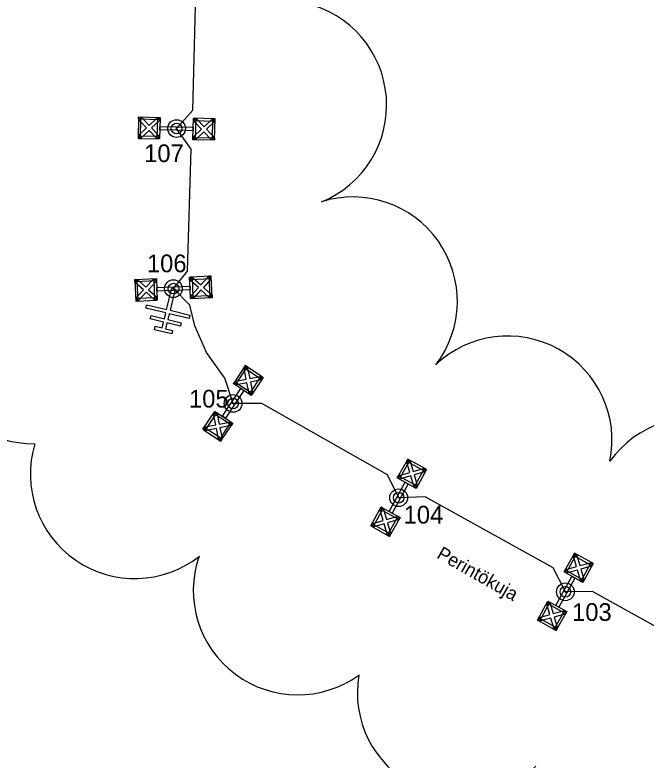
# Model space of a CAD drawing. Extents: x 25497851 to 25498523, y 6686544 to 6687372.
# Drawn here: x 25498083.9 to 25498190.6, y 6686990.4 to 6687116.4 of the extents above; entities that cross this region are included whole.
import ezdxf

# ---------------------------------------------------------------- set-up
doc = ezdxf.new("R2010")
doc.units = 0
for name, color, linetype in [('KAAPELI', 7, 'Continuous'), ('MUU_SUUNNITELMAVIIVA', 7, 'Continuous'), ('MUU_UV-SUUNNITELMASYMBOLI', 7, 'Continuous'), ('PYLVAS', 7, 'Continuous'), ('TEKSTI_SUUNNITELMA-ALUE', 7, 'Continuous'), ('VALAISIN', 7, 'Continuous')]:
    doc.layers.add(name, color=color, linetype=linetype)

msp = doc.modelspace()

# ---------------------------------------------------------------- linework, layer by layer
at = {"layer": 'KAAPELI'}
for points in [[(25498111.22, 6687097.23), (25498113.96, 6687100.34), (25498114.59, 6687124.51), (25498112.24, 6687128.3)], [(25498110.69, 6687070.16), (25498113.08, 6687073.12), (25498113.67, 6687093.76), (25498111.22, 6687097.23)], [(25498120.77, 6687050.75), (25498119.4, 6687055), (25498116.27, 6687059.35), (25498114.33, 6687063.87), (25498113.44, 6687067.35), (25498110.69, 6687070.16)], [(25498148.76, 6687034.81), (25498146.87, 6687038.69), (25498125.62, 6687050.76), (25498120.77, 6687050.75)], [(25498176.94, 6687018.9), (25498174.85, 6687022.93), (25498153.23, 6687034.97), (25498148.76, 6687034.81)], [(25498200.27, 6687005.75), (25498197.85, 6687009.86), (25498181.51, 6687018.98), (25498176.94, 6687018.9)]]:
    msp.add_lwpolyline(points, dxfattribs=at)
at = {"layer": 'MUU_SUUNNITELMAVIIVA'}
for centre, start, end in [((25498129.08, 6687101.2), 292.0128, 77.0128), ((25498141.03, 6687068.02), 322.6047, 107.6047), ((25498087.01, 6687061.58), 125.8219, 270.8219), ((25498167.18, 6687044.5), 348.4543, 133.4543), ((25498198.85, 6687030.73), 359.5582, 144.5582), ((25498104.15, 6687038.79), 163.048, 308.048), ((25498131.7, 6687019.13), 160.9084, 305.9084), ((25498159.43, 6687001.84), 170.2279, 315.2279)]:
    msp.add_arc(centre, 17.65, start, end, dxfattribs=at)
at = {"layer": 'MUU_UV-SUUNNITELMASYMBOLI'}
for p, q in [((25498109.53, 6687066.64), (25498110.4, 6687070.23)), ((25498110.98, 6687070.09), (25498110.12, 6687066.5)), ((25498110.4, 6687070.23), (25498110.98, 6687070.09)), ((25498106.04, 6687066.86), (25498106.18, 6687067.44)), ((25498109.39, 6687066.05), (25498106.04, 6687066.86)), ((25498106.18, 6687067.44), (25498109.53, 6687066.64)), ((25498110.12, 6687066.5), (25498113.47, 6687065.69)), ((25498106.76, 6687065.04), (25498106.9, 6687065.62)), ((25498109.02, 6687064.5), (25498106.76, 6687065.04)), ((25498106.9, 6687065.62), (25498109.16, 6687065.08)), ((25498109.16, 6687065.08), (25498109.39, 6687066.05)), ((25498109.98, 6687065.91), (25498109.74, 6687064.94)), ((25498113.33, 6687065.11), (25498109.98, 6687065.91)), ((25498113.47, 6687065.69), (25498113.33, 6687065.11)), ((25498107.48, 6687063.22), (25498107.62, 6687063.81)), ((25498107.62, 6687063.81), (25498108.79, 6687063.53)), ((25498108.79, 6687063.53), (25498109.02, 6687064.5)), ((25498109.6, 6687064.36), (25498109.37, 6687063.38)), ((25498111.86, 6687063.81), (25498109.6, 6687064.36)), ((25498109.74, 6687064.94), (25498112, 6687064.4)), ((25498112, 6687064.4), (25498111.86, 6687063.81)), ((25498110.4, 6687062.52), (25498107.48, 6687063.22)), ((25498109.37, 6687063.38), (25498110.54, 6687063.1)), ((25498110.54, 6687063.1), (25498110.4, 6687062.52))]:
    msp.add_line(p, q, dxfattribs=at)
at = {"layer": 'PYLVAS'}
for centre, radius in [((25498111.22, 6687097.23), 1.5), ((25498111.22, 6687097.23), 0.9), ((25498110.69, 6687070.16), 1.5), ((25498110.69, 6687070.16), 0.9), ((25498120.77, 6687050.75), 1.5), ((25498120.77, 6687050.75), 0.9), ((25498148.76, 6687034.81), 1.5), ((25498148.76, 6687034.81), 0.9), ((25498176.94, 6687018.9), 1.5), ((25498176.94, 6687018.9), 0.9)]:
    msp.add_circle(centre, radius, dxfattribs=at)
at = {"layer": 'VALAISIN'}
for points in [[(25498105.2, 6687099.08), (25498104.8, 6687099.09), (25498104.72, 6687095.56), (25498105.11, 6687095.55)], [(25498108.44, 6687098.72), (25498104.79, 6687098.81), (25498104.8, 6687099.21), (25498108.45, 6687099.12)], [(25498108.31, 6687098.58), (25498107.01, 6687097.33), (25498108.25, 6687096.02), (25498108.24, 6687095.6), (25498107.82, 6687095.61), (25498106.57, 6687096.92), (25498105.26, 6687095.67), (25498104.84, 6687095.68), (25498104.85, 6687096.1), (25498106.16, 6687097.35), (25498104.91, 6687098.66), (25498104.92, 6687099.09), (25498105.35, 6687099.07), (25498106.59, 6687097.77), (25498107.9, 6687099.01), (25498108.32, 6687099)], [(25498108.36, 6687095.47), (25498107.96, 6687095.48), (25498108.05, 6687099.01), (25498108.45, 6687099)], [(25498114.08, 6687098.98), (25498114.48, 6687098.97), (25498114.39, 6687095.44), (25498113.99, 6687095.45)], [(25498114.12, 6687095.87), (25498115.43, 6687097.12), (25498114.19, 6687098.43), (25498114.2, 6687098.85), (25498114.62, 6687098.84), (25498115.86, 6687097.53), (25498117.17, 6687098.78), (25498117.6, 6687098.77), (25498117.59, 6687098.35), (25498116.28, 6687097.1), (25498117.52, 6687095.79), (25498117.51, 6687095.37), (25498117.09, 6687095.38), (25498115.84, 6687096.69), (25498114.54, 6687095.44), (25498114.11, 6687095.45)], [(25498117.6, 6687098.89), (25498114.2, 6687098.98), (25498114.19, 6687098.58), (25498117.59, 6687098.49)], [(25498117.24, 6687095.37), (25498117.64, 6687095.36), (25498117.72, 6687098.89), (25498117.32, 6687098.9)], [(25498111.21, 6687096.93), (25498108.4, 6687096.99), (25498108.41, 6687097.59), (25498111.23, 6687097.53)], [(25498111.23, 6687097.53), (25498114.04, 6687097.46), (25498114.02, 6687096.86), (25498111.21, 6687096.93)], [(25498104.84, 6687095.56), (25498108.24, 6687095.47), (25498108.25, 6687095.87), (25498104.85, 6687095.96)], [(25498114, 6687095.73), (25498117.64, 6687095.64), (25498117.63, 6687095.24), (25498113.99, 6687095.33)], [(25498107.82, 6687071.47), (25498104.18, 6687071.31), (25498104.16, 6687071.71), (25498107.8, 6687071.87)], [(25498104.56, 6687071.61), (25498104.16, 6687071.59), (25498104.32, 6687068.06), (25498104.72, 6687068.08)], [(25498107.7, 6687071.32), (25498106.48, 6687069.98), (25498107.81, 6687068.76), (25498107.83, 6687068.34), (25498107.41, 6687068.32), (25498106.08, 6687069.54), (25498104.86, 6687068.21), (25498104.43, 6687068.19), (25498104.41, 6687068.62), (25498105.64, 6687069.95), (25498104.3, 6687071.17), (25498104.29, 6687071.59), (25498104.71, 6687071.61), (25498106.04, 6687070.39), (25498107.26, 6687071.72), (25498107.68, 6687071.74)], [(25498107.96, 6687068.22), (25498107.56, 6687068.2), (25498107.41, 6687071.73), (25498107.81, 6687071.75)], [(25498113.43, 6687072.11), (25498113.83, 6687072.12), (25498113.98, 6687068.6), (25498113.58, 6687068.58)], [(25498116.95, 6687072.26), (25498113.55, 6687072.11), (25498113.57, 6687071.71), (25498116.96, 6687071.86)], [(25498113.68, 6687069.01), (25498114.9, 6687070.34), (25498113.57, 6687071.56), (25498113.55, 6687071.99), (25498113.98, 6687072.01), (25498115.31, 6687070.79), (25498116.53, 6687072.12), (25498116.95, 6687072.14), (25498116.97, 6687071.71), (25498115.75, 6687070.38), (25498117.08, 6687069.16), (25498117.1, 6687068.73), (25498116.67, 6687068.71), (25498115.34, 6687069.94), (25498114.12, 6687068.6), (25498113.7, 6687068.59)], [(25498116.82, 6687068.72), (25498117.22, 6687068.74), (25498117.07, 6687072.26), (25498116.67, 6687072.25)], [(25498110.71, 6687069.86), (25498107.89, 6687069.74), (25498107.87, 6687070.34), (25498110.68, 6687070.46)], [(25498110.68, 6687070.46), (25498113.49, 6687070.58), (25498113.52, 6687069.98), (25498110.71, 6687069.86)], [(25498113.57, 6687068.86), (25498117.21, 6687069.02), (25498117.23, 6687068.62), (25498113.58, 6687068.46)], [(25498104.44, 6687068.07), (25498107.84, 6687068.22), (25498107.82, 6687068.61), (25498104.42, 6687068.47)], [(25498122.77, 6687057.03), (25498120.88, 6687054.2), (25498121.21, 6687053.98), (25498123.1, 6687056.81)], [(25498123.47, 6687052.48), (25498123.11, 6687054.25), (25498121.34, 6687053.9), (25498120.98, 6687054.13), (25498121.22, 6687054.49), (25498122.99, 6687054.84), (25498122.63, 6687056.61), (25498122.87, 6687056.97), (25498123.22, 6687056.73), (25498123.58, 6687054.96), (25498125.35, 6687055.31), (25498125.7, 6687055.08), (25498125.47, 6687054.73), (25498123.7, 6687054.37), (25498124.05, 6687052.6), (25498123.82, 6687052.25)], [(25498125.55, 6687054.85), (25498125.77, 6687055.18), (25498122.83, 6687057.14), (25498122.61, 6687056.8)], [(25498123.52, 6687052.3), (25498125.54, 6687055.34), (25498125.87, 6687055.11), (25498123.85, 6687052.08)], [(25498120.81, 6687054.1), (25498121.04, 6687054.43), (25498123.97, 6687052.48), (25498123.75, 6687052.15)], [(25498120.52, 6687050.91), (25498122.08, 6687053.26), (25498122.58, 6687052.92), (25498121.02, 6687050.58)], [(25498121.02, 6687050.58), (25498119.47, 6687048.24), (25498118.97, 6687048.57), (25498120.52, 6687050.91)], [(25498118.03, 6687049.19), (25498116.01, 6687046.16), (25498115.68, 6687046.38), (25498117.69, 6687049.41)], [(25498118.08, 6687049.01), (25498118.44, 6687047.24), (25498120.21, 6687047.59), (25498120.56, 6687047.36), (25498120.33, 6687047.01), (25498118.56, 6687046.65), (25498118.92, 6687044.88), (25498118.68, 6687044.53), (25498118.33, 6687044.76), (25498117.97, 6687046.53), (25498116.2, 6687046.18), (25498115.84, 6687046.41), (25498116.08, 6687046.77), (25498117.85, 6687047.12), (25498117.49, 6687048.89), (25498117.73, 6687049.24)], [(25498120.73, 6687047.39), (25498120.51, 6687047.06), (25498117.57, 6687049.01), (25498117.8, 6687049.35)], [(25498118.78, 6687044.46), (25498120.67, 6687047.29), (25498120.33, 6687047.51), (25498118.45, 6687044.68)], [(25498116, 6687046.64), (25498115.78, 6687046.31), (25498118.71, 6687044.36), (25498118.94, 6687044.69)], [(25498150.24, 6687041.24), (25498148.59, 6687038.26), (25498148.94, 6687038.07), (25498150.59, 6687041.05)], [(25498151.3, 6687036.76), (25498150.8, 6687038.5), (25498149.07, 6687038), (25498148.7, 6687038.21), (25498148.9, 6687038.58), (25498150.64, 6687039.07), (25498150.14, 6687040.81), (25498150.35, 6687041.18), (25498150.72, 6687040.97), (25498151.22, 6687039.24), (25498152.95, 6687039.73), (25498153.32, 6687039.53), (25498153.12, 6687039.16), (25498151.38, 6687038.66), (25498151.88, 6687036.92), (25498151.68, 6687036.55)], [(25498153.19, 6687039.29), (25498153.38, 6687039.64), (25498150.3, 6687041.35), (25498150.1, 6687041)], [(25498151.37, 6687036.58), (25498153.14, 6687039.77), (25498153.49, 6687039.58), (25498151.72, 6687036.39)], [(25498148.5, 6687034.96), (25498149.86, 6687037.42), (25498150.39, 6687037.13), (25498149.02, 6687034.67)], [(25498148.53, 6687038.16), (25498148.72, 6687038.51), (25498151.81, 6687036.8), (25498151.62, 6687036.45)], [(25498149.02, 6687034.67), (25498147.66, 6687032.2), (25498147.13, 6687032.5), (25498148.5, 6687034.96)], [(25498146.15, 6687033.04), (25498144.38, 6687029.85), (25498144.03, 6687030.05), (25498145.8, 6687033.24)], [(25498146.22, 6687032.86), (25498146.72, 6687031.13), (25498148.45, 6687031.62), (25498148.82, 6687031.42), (25498148.62, 6687031.05), (25498146.88, 6687030.55), (25498147.38, 6687028.81), (25498147.17, 6687028.44), (25498146.8, 6687028.65), (25498146.3, 6687030.39), (25498144.57, 6687029.89), (25498144.2, 6687030.09), (25498144.4, 6687030.47), (25498146.14, 6687030.96), (25498145.64, 6687032.7), (25498145.84, 6687033.07)], [(25498148.99, 6687031.47), (25498148.8, 6687031.12), (25498145.71, 6687032.83), (25498145.9, 6687033.18)], [(25498147.28, 6687028.38), (25498148.93, 6687031.36), (25498148.58, 6687031.55), (25498146.93, 6687028.58)], [(25498144.33, 6687030.34), (25498144.14, 6687029.99), (25498147.22, 6687028.28), (25498147.42, 6687028.63)], [(25498178.41, 6687025.33), (25498176.76, 6687022.35), (25498177.11, 6687022.16), (25498178.76, 6687025.13)], [(25498179.48, 6687020.85), (25498178.98, 6687022.58), (25498177.24, 6687022.09), (25498176.87, 6687022.29), (25498177.08, 6687022.66), (25498178.81, 6687023.16), (25498178.31, 6687024.9), (25498178.52, 6687025.27), (25498178.89, 6687025.06), (25498179.39, 6687023.33), (25498181.13, 6687023.82), (25498181.5, 6687023.62), (25498181.29, 6687023.25), (25498179.56, 6687022.75), (25498180.06, 6687021.01), (25498179.85, 6687020.64)], [(25498181.37, 6687023.37), (25498181.56, 6687023.72), (25498178.47, 6687025.43), (25498178.28, 6687025.08)], [(25498179.55, 6687020.67), (25498181.31, 6687023.86), (25498181.66, 6687023.67), (25498179.9, 6687020.48)], [(25498176.71, 6687022.25), (25498176.9, 6687022.6), (25498179.99, 6687020.88), (25498179.79, 6687020.53)], [(25498176.67, 6687019.05), (25498178.04, 6687021.51), (25498178.56, 6687021.22), (25498177.2, 6687018.75)], [(25498177.2, 6687018.75), (25498175.83, 6687016.29), (25498175.31, 6687016.58), (25498176.67, 6687019.05)], [(25498174.32, 6687017.13), (25498172.56, 6687013.94), (25498172.21, 6687014.13), (25498173.97, 6687017.32)], [(25498174.39, 6687016.95), (25498174.89, 6687015.22), (25498176.63, 6687015.71), (25498177, 6687015.51), (25498176.79, 6687015.14), (25498175.06, 6687014.64), (25498175.56, 6687012.9), (25498175.35, 6687012.53), (25498174.98, 6687012.74), (25498174.48, 6687014.47), (25498172.74, 6687013.98), (25498172.37, 6687014.18), (25498172.58, 6687014.55), (25498174.31, 6687015.05), (25498173.81, 6687016.79), (25498174.02, 6687017.16)], [(25498177.17, 6687015.55), (25498176.97, 6687015.2), (25498173.89, 6687016.92), (25498174.08, 6687017.27)], [(25498175.46, 6687012.47), (25498177.11, 6687015.45), (25498176.76, 6687015.64), (25498175.11, 6687012.67)], [(25498172.51, 6687014.43), (25498172.31, 6687014.08), (25498175.4, 6687012.37), (25498175.59, 6687012.72)]]:
    msp.add_lwpolyline(points, close=True, dxfattribs=at)

# ---------------------------------------------------------------- texts
at = {"layer": 'TEKSTI_SUUNNITELMA-ALUE'}
for s, p in [('107', (25498105.74, 6687091.55)), ('106', (25498106.21, 6687072.93)), ('105', (25498113.32, 6687050.05)), ('104', (25498149.6, 6687030.44)), ('103', (25498178.07, 6687013.98))]:
    msp.add_text(s, height=3, dxfattribs=at).set_placement(p)
msp.add_text('Perintökuja', height=2.25, rotation=330.3502, dxfattribs=at).set_placement((25498155.04, 6687024.72))

doc.saveas('drawing.dxf')
